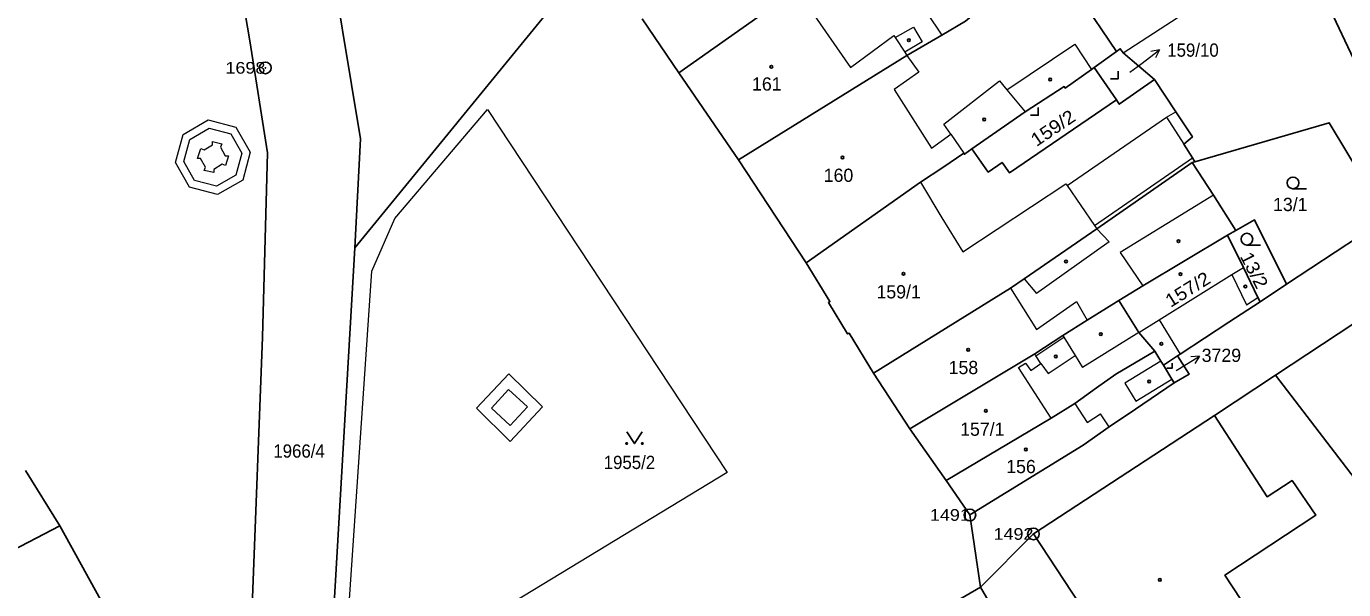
# Model space of a CAD drawing. Extents: x -679733 to -673243, y -1075091 to -1066557.
# Drawn here: x -676396.8 to -676227.8, y -1071687 to -1071614.6 of the extents above; entities that cross this region are included whole.
import ezdxf
from ezdxf.enums import TextEntityAlignment as Align

# ---------------------------------------------------------------- set-up
doc = ezdxf.new("R2010")
doc.units = 0
doc.header["$LTSCALE"] = 0.68
for name, color, linetype, lineweight in [('1', 7, 'Continuous', 25), ('3', 7, 'Continuous', 25), ('4', 7, 'Continuous', 13), ('5', 7, 'Continuous', 25), ('7', 7, 'Continuous', 13), ('8', 7, 'Continuous', 25)]:
    doc.layers.add(name, color=color, linetype=linetype, lineweight=lineweight)
doc.layers.add('2', color=7, linetype='Continuous')

msp = doc.modelspace()

# ---------------------------------------------------------------- linework, layer by layer
at = {"layer": '1'}
for p, q in [((-676323.65, -1071605.06), (-676354.68, -1071643.07)), ((-676265.58, -1071605.04), (-676256.92, -1071617.84)), ((-676317.8, -1071613.66), (-676313.09, -1071620.56)), ((-676256.92, -1071617.84), (-676259.79, -1071619.88)), ((-676256.93, -1071624.07), (-676259.79, -1071619.88)), ((-676305.44, -1071631.74), (-676296.73, -1071644.97)), ((-676247.22, -1071632.12), (-676246.86, -1071632.02)), ((-676242.69, -1071641.44), (-676241.62, -1071640.83)), ((-676238.49, -1071650), (-676235.09, -1071647.75)), ((-676250.9, -1071658.13), (-676249.09, -1071656.93)), ((-676288.1, -1071659.17), (-676283.43, -1071666.32)), ((-676283.43, -1071666.32), (-676278.79, -1071672.97)), ((-676385.21, -1071692.07), (-676392.51, -1071678.79)), ((-676274.38, -1071686.65), (-676283.55, -1071691.97))]:
    msp.add_line(p, q, dxfattribs=at)
for points in [[(-676409.82, -1071487.07), (-676395.79, -1071511.68), (-676384.03, -1071532.68), (-676381.89, -1071539.87), (-676376.19, -1071569.34), (-676368.13, -1071616.48), (-676365.86, -1071630.87), (-676366.52, -1071654.54), (-676369.19, -1071723.74), (-676369.58, -1071729.58), (-676368.92, -1071732.38)], [(-676254.27, -1071592.33), (-676250.44, -1071598.38), (-676250.16, -1071598.2), (-676242.88, -1071609.41), (-676233.68, -1071603.54), (-676226.09, -1071619.69), (-676225.97, -1071624.14), (-676221.28, -1071632.65), (-676219.43, -1071633.33)], [(-676281.75, -1071598.41), (-676282.81, -1071599.16), (-676286.84, -1071602.07), (-676288.17, -1071603), (-676292.09, -1071605.74), (-676313.09, -1071620.56), (-676305.44, -1071631.74)], [(-676354.68, -1071643.07), (-676353.93, -1071629.04), (-676358.61, -1071600.83)], [(-676272.57, -1071610.82), (-676276.28, -1071613.95), (-676279.35, -1071615.75), (-676283.81, -1071618.35), (-676305.44, -1071631.74)], [(-676256.92, -1071617.84), (-676256.44, -1071617.49), (-676256.07, -1071618.02), (-676252.04, -1071621.43)], [(-676259.79, -1071619.88), (-676260.14, -1071620.14), (-676263.49, -1071622.54), (-676263.63, -1071622.34), (-676268.66, -1071625.61), (-676275.49, -1071630.36)], [(-676252.04, -1071621.43), (-676256.57, -1071624.61), (-676256.93, -1071624.07)], [(-676246.86, -1071632.02), (-676247.18, -1071631.5), (-676248.3, -1071629.73), (-676247.17, -1071628.82), (-676249.29, -1071625.6), (-676252.04, -1071621.43)], [(-676256.93, -1071624.07), (-676270.67, -1071633.41), (-676271.6, -1071632.09), (-676273.39, -1071633.33), (-676275.49, -1071630.36)], [(-676246.86, -1071632.02), (-676229.61, -1071626.99), (-676224.86, -1071634.98), (-676225.72, -1071641.56)], [(-676275.49, -1071630.36), (-676276.45, -1071631.03), (-676276.53, -1071630.92), (-676279.21, -1071632.74), (-676282.09, -1071634.64), (-676296.73, -1071644.97)], [(-676247.22, -1071632.12), (-676259.45, -1071640.64), (-676268.78, -1071647.06), (-676270.54, -1071648.26), (-676288.1, -1071659.17)], [(-676241.62, -1071640.83), (-676244.47, -1071636.28), (-676247.22, -1071632.12)], [(-676241.62, -1071640.83), (-676239.22, -1071639.46), (-676235.09, -1071647.75), (-676225.72, -1071641.56)], [(-676242.69, -1071641.44), (-676253.54, -1071647.95), (-676256.61, -1071649.82)], [(-676238.49, -1071650), (-676238.77, -1071649.43), (-676240.63, -1071645.59), (-676242.69, -1071641.44)], [(-676359.43, -1071729.07), (-676360.28, -1071727.35), (-676359.84, -1071726.37), (-676357.99, -1071700.53), (-676354.68, -1071643.07)], [(-676296.73, -1071644.97), (-676293.69, -1071649.96), (-676293.9, -1071650.09), (-676291.44, -1071654.13), (-676291.24, -1071654.01), (-676288.1, -1071659.17)], [(-676244.34, -1071664.59), (-676236.52, -1071659.42), (-676214.28, -1071644.72)], [(-676256.61, -1071649.82), (-676260.69, -1071652.36), (-676263.83, -1071654.31), (-676267.42, -1071656.68), (-676283.43, -1071666.32)], [(-676252, -1071656.35), (-676254.05, -1071653.94), (-676256.61, -1071649.82)], [(-676249.09, -1071656.93), (-676248.74, -1071656.71), (-676242.52, -1071652.62), (-676238.49, -1071650)], [(-676252, -1071656.35), (-676256.99, -1071659.28), (-676259.51, -1071661.04), (-676262.28, -1071663.06), (-676265.3, -1071664.96), (-676278.79, -1071672.97), (-676275.74, -1071677.38)], [(-676250.9, -1071658.13), (-676251.22, -1071657.62), (-676252, -1071656.35)], [(-676249.09, -1071656.93), (-676247.6, -1071659.3), (-676249.51, -1071660.4)], [(-676249.51, -1071660.4), (-676249.8, -1071659.93), (-676250.9, -1071658.13)], [(-676236.52, -1071659.42), (-676224.9, -1071674.63), (-676205.45, -1071666.89)], [(-676275.74, -1071677.38), (-676261.19, -1071668.4), (-676257.85, -1071666.06), (-676254.49, -1071663.79), (-676249.51, -1071660.4)], [(-676229.7, -1071705.35), (-676243, -1071685.11), (-676231.35, -1071677.42), (-676234.39, -1071672.97), (-676237.6, -1071675.04), (-676244.34, -1071664.59), (-676267.58, -1071679.82)], [(-676417.9, -1071694.39), (-676399.59, -1071682.48), (-676392.51, -1071678.79), (-676396.92, -1071671.69)], [(-676275.74, -1071677.38), (-676274.38, -1071686.65), (-676267.58, -1071679.82)], [(-676267.58, -1071679.82), (-676259.71, -1071691.8), (-676259.99, -1071691.98), (-676251.12, -1071705.37), (-676250.88, -1071705.21), (-676242.83, -1071717.44)], [(-676253.8, -1071717.85), (-676256.22, -1071714.01), (-676256.09, -1071713.94), (-676260.54, -1071706.43), (-676261.93, -1071707.38), (-676265.5, -1071701.11), (-676264.81, -1071700.51), (-676266.67, -1071697.53), (-676267.32, -1071697.96), (-676270.72, -1071692.9), (-676274.38, -1071686.65)]]:
    msp.add_lwpolyline(points, dxfattribs=at)
at = {"layer": '3'}
for p, q in [((-676234.273, -1071635.47), (-676232.523, -1071635.47)), ((-676240.183, -1071642.7), (-676238.433, -1071642.7))]:
    msp.add_line(p, q, dxfattribs=at)
for points in [[(-676257.711, -1071621.37), (-676256.71, -1071621.37), (-676256.71, -1071620.37)], [(-676267.971, -1071626.02), (-676266.97, -1071626.02), (-676266.97, -1071625.02)], [(-676250.451, -1071658.54), (-676249.78, -1071658.54), (-676249.78, -1071657.87)], [(-676319.78, -1071666.699), (-676318.78, -1071668.2), (-676317.78, -1071666.699)]]:
    msp.add_lwpolyline(points, dxfattribs=at)
for centre, radius in [((-676234.2729, -1071634.7198), 0.75), ((-676240.1829, -1071641.9498), 0.75), ((-676319.78, -1071668.1995), 0.1), ((-676317.78, -1071668.1995), 0.1)]:
    msp.add_circle(centre, radius, dxfattribs=at)
at = {"layer": '4'}
for p, q in [((-676256.07, -1071618.02), (-676242.88, -1071609.41)), ((-676297.1, -1071611.14), (-676291.07, -1071619.88)), ((-676281.28, -1071612.88), (-676279.35, -1071615.75)), ((-676291.07, -1071619.88), (-676285.51, -1071615.77)), ((-676285.51, -1071615.77), (-676285.32, -1071616.06)), ((-676285.32, -1071616.06), (-676282.97, -1071614.7)), ((-676282.97, -1071614.7), (-676281.85, -1071616.61)), ((-676285.32, -1071616.06), (-676284.09, -1071617.92)), ((-676281.85, -1071616.61), (-676284.09, -1071617.92)), ((-676270.98, -1071622.76), (-676262.29, -1071616.9)), ((-676262.29, -1071616.9), (-676260.14, -1071620.14)), ((-676284.09, -1071617.92), (-676283.81, -1071618.35)), ((-676283.81, -1071618.35), (-676282.31, -1071620.5)), ((-676282.31, -1071620.5), (-676285.45, -1071622.72)), ((-676279.08, -1071627.16), (-676271.92, -1071621.6)), ((-676271.92, -1071621.6), (-676270.98, -1071622.76)), ((-676285.45, -1071622.72), (-676280.66, -1071630.28)), ((-676270.98, -1071622.76), (-676268.66, -1071625.61)), ((-676349.55, -1071639.3), (-676337.64, -1071625.28)), ((-676337.64, -1071625.28), (-676306.9, -1071671.93)), ((-676250.49, -1071626.26), (-676249.29, -1071625.6)), ((-676376.72, -1071628.5), (-676373.5, -1071626.63)), ((-676373.5, -1071626.63), (-676369.92, -1071627.55)), ((-676369.92, -1071627.55), (-676368.11, -1071630.79)), ((-676278.18, -1071628.48), (-676279.08, -1071627.16)), ((-676263.25, -1071635.07), (-676250.49, -1071626.26)), ((-676250.49, -1071626.26), (-676248.3, -1071629.73)), ((-676377.7, -1071632.12), (-676376.72, -1071628.5)), ((-676376.62, -1071631.98), (-676375.86, -1071629.16)), ((-676375.86, -1071629.16), (-676373.36, -1071627.7)), ((-676373.36, -1071627.7), (-676370.58, -1071628.41)), ((-676370.58, -1071628.41), (-676369.18, -1071630.92)), ((-676280.66, -1071630.28), (-676278.18, -1071628.48)), ((-676278.18, -1071628.48), (-676276.53, -1071630.92)), ((-676374.87, -1071631.6), (-676374.44, -1071630.31)), ((-676374.44, -1071630.31), (-676374.02, -1071630.47)), ((-676374.02, -1071630.47), (-676372.92, -1071629.83)), ((-676372.93, -1071629.42), (-676371.74, -1071629.7)), ((-676372.92, -1071629.83), (-676372.93, -1071629.42)), ((-676371.74, -1071629.7), (-676371.92, -1071630.11)), ((-676371.92, -1071630.11), (-676371.31, -1071631.23)), ((-676369.18, -1071630.92), (-676369.92, -1071633.71)), ((-676368.11, -1071630.79), (-676369.06, -1071634.37)), ((-676375.89, -1071635.27), (-676377.7, -1071632.12)), ((-676375.23, -1071634.4), (-676376.62, -1071631.98)), ((-676374.46, -1071631.59), (-676374.87, -1071631.6)), ((-676373.82, -1071632.69), (-676374.46, -1071631.59)), ((-676373.99, -1071633.11), (-676373.82, -1071632.69)), ((-676371.69, -1071632.33), (-676372.78, -1071632.99)), ((-676371.28, -1071632.49), (-676371.69, -1071632.33)), ((-676371.31, -1071631.23), (-676370.9, -1071631.23)), ((-676370.9, -1071631.23), (-676371.28, -1071632.49)), ((-676259.76, -1071640.19), (-676247.18, -1071631.5)), ((-676372.77, -1071633.4), (-676373.99, -1071633.11)), ((-676372.78, -1071632.99), (-676372.77, -1071633.4)), ((-676369.92, -1071633.71), (-676372.42, -1071635.13)), ((-676369.06, -1071634.37), (-676372.28, -1071636.2)), ((-676372.28, -1071636.2), (-676375.89, -1071635.27)), ((-676372.42, -1071635.13), (-676375.23, -1071634.4)), ((-676282.09, -1071634.64), (-676279.35, -1071639.2)), ((-676276.65, -1071643.59), (-676263.42, -1071634.82)), ((-676263.42, -1071634.82), (-676263.25, -1071635.07)), ((-676263.25, -1071635.07), (-676259.76, -1071640.19)), ((-676244.47, -1071636.28), (-676256.46, -1071643.66)), ((-676352.5, -1071646.08), (-676349.55, -1071639.3)), ((-676279.35, -1071639.2), (-676276.65, -1071643.59)), ((-676259.76, -1071640.19), (-676259.45, -1071640.64)), ((-676259.45, -1071640.64), (-676257.88, -1071642.31)), ((-676257.88, -1071642.31), (-676267.19, -1071648.94)), ((-676256.46, -1071643.66), (-676253.54, -1071647.95)), ((-676355.69, -1071692.9), (-676352.5, -1071646.08)), ((-676242.11, -1071646.51), (-676240.63, -1071645.59)), ((-676268.78, -1071647.06), (-676267.19, -1071648.94)), ((-676251.45, -1071652.32), (-676242.11, -1071646.51)), ((-676242.11, -1071646.51), (-676240.23, -1071650.38)), ((-676270.54, -1071648.26), (-676267.19, -1071653.57)), ((-676240.23, -1071650.38), (-676238.77, -1071649.43)), ((-676267.19, -1071653.57), (-676262.06, -1071649.96)), ((-676262.06, -1071649.96), (-676260.69, -1071652.36)), ((-676254.05, -1071653.94), (-676251.45, -1071652.32)), ((-676251.45, -1071652.32), (-676248.74, -1071656.71)), ((-676267.26, -1071656.93), (-676263.7, -1071654.52)), ((-676263.83, -1071654.31), (-676263.7, -1071654.52)), ((-676263.7, -1071654.52), (-676262.22, -1071656.9)), ((-676254.05, -1071653.94), (-676261.27, -1071658.43)), ((-676269.5, -1071658.42), (-676268.61, -1071657.86)), ((-676268.61, -1071657.86), (-676267.92, -1071658.83)), ((-676267.92, -1071658.83), (-676266.62, -1071657.91)), ((-676267.26, -1071656.93), (-676267.42, -1071656.68)), ((-676266.62, -1071657.91), (-676267.26, -1071656.93)), ((-676266.62, -1071657.91), (-676265.69, -1071659.22)), ((-676265.69, -1071659.22), (-676262.22, -1071656.9)), ((-676262.22, -1071656.9), (-676261.27, -1071658.43)), ((-676251.22, -1071657.62), (-676255.84, -1071660.46)), ((-676339.05, -1071663.67), (-676334.9, -1071659.25)), ((-676334.9, -1071659.25), (-676330.57, -1071663.48)), ((-676265.3, -1071664.96), (-676269.5, -1071658.42)), ((-676337.15, -1071663.64), (-676334.94, -1071661.28)), ((-676334.94, -1071661.28), (-676332.5, -1071663.47)), ((-676255.84, -1071660.46), (-676254.42, -1071662.77)), ((-676254.42, -1071662.77), (-676249.8, -1071659.93)), ((-676262.28, -1071663.06), (-676260.69, -1071665.52)), ((-676334.72, -1071667.94), (-676339.05, -1071663.67)), ((-676334.75, -1071665.89), (-676337.15, -1071663.64)), ((-676332.5, -1071663.47), (-676334.75, -1071665.89)), ((-676330.57, -1071663.48), (-676334.72, -1071667.94)), ((-676260.69, -1071665.52), (-676258.97, -1071664.41)), ((-676257.85, -1071666.06), (-676258.97, -1071664.41)), ((-676306.9, -1071671.93), (-676348.68, -1071697.31))]:
    msp.add_line(p, q, dxfattribs=at)
at = {"layer": '5'}
for centre in [(-676283.5668, -1071616.3992), (-676301.2168, -1071619.7992), (-676265.4268, -1071621.4492), (-676273.8968, -1071626.5692), (-676292.0768, -1071631.4692), (-676248.9668, -1071642.2092), (-676284.2568, -1071646.3892), (-676263.4068, -1071644.8292), (-676248.7068, -1071646.4392), (-676240.3868, -1071648.0392), (-676258.9468, -1071654.1392), (-676275.9468, -1071656.1592), (-676251.1668, -1071655.3892), (-676264.7068, -1071657.0092), (-676252.7468, -1071660.2392), (-676273.6868, -1071663.9992), (-676268.5468, -1071668.9592), (-676251.3468, -1071685.7292)]:
    msp.add_circle(centre, 0.175, dxfattribs=at)
at = {"layer": '7'}
for p, q in [((-676251.413, -1071617.644), (-676252.514, -1071617.847)), ((-676246.285, -1071656.96), (-676247.4, -1071657.066))]:
    msp.add_line(p, q, dxfattribs=at)
for points in [[(-676255.23, -1071620.51), (-676253.81, -1071619.45), (-676251.413, -1071617.644), (-676251.912, -1071618.647)], [(-676249.25, -1071658.81), (-676248.83, -1071658.55), (-676246.285, -1071656.96), (-676246.869, -1071657.915)]]:
    msp.add_lwpolyline(points, dxfattribs=at)
at = {"layer": '8'}
for centre, radius in [((-676366.15, -1071619.9398), 0.75), ((-676366.15, -1071619.9398), 0.03), ((-676275.74, -1071677.3798), 0.75), ((-676275.74, -1071677.3798), 0.03), ((-676267.58, -1071679.8198), 0.75), ((-676267.58, -1071679.8198), 0.03)]:
    msp.add_circle(centre, radius, dxfattribs=at)

# ---------------------------------------------------------------- texts
at = {"layer": '2', "width": 0.95}
for s, p in [('159/10', (-676250.41, -1071618.509)), ('1966/4', (-676365.13, -1071670.019))]:
    msp.add_text(s, height=1.7, dxfattribs=at).set_placement(p)
at = {"layer": '2'}
for s, p in [('161', (-676301.799, -1071622.86)), ('160', (-676292.599, -1071634.59)), ('13/1', (-676234.62, -1071638.34)), ('159/1', (-676284.88, -1071649.56)), ('158', (-676276.569, -1071659.29)), ('157/1', (-676274.14, -1071667.21)), ('156', (-676269.179, -1071672.009))]:
    msp.add_text(s, height=1.7, dxfattribs=at).set_placement(p, align=Align.CENTER)
at = {"layer": '2', "width": 1.1}
for s, rotation, p in [('159/2', 34, (-676264.5968, -1071628.3704)), ('13/2', 297, (-676240.0055, -1071646.3231)), ('157/2', 32, (-676247.3289, -1071649.1228))]:
    msp.add_text(s, height=1.7, rotation=rotation, dxfattribs=at).set_placement(p, align=Align.CENTER)
at = {"layer": '2'}
msp.add_text('3729', height=1.7, dxfattribs=at).set_placement((-676245.99, -1071657.72))
at = {"layer": '2', "width": 0.95}
msp.add_text('1955/2', height=1.7, dxfattribs=at).set_placement((-676319.429, -1071671.479), align=Align.CENTER)
at = {"layer": '8', "width": 1.15}
for s, p in [('1698', (-676366.149, -1071620.69)), ('1491', (-676275.739, -1071678.129)), ('1492', (-676267.579, -1071680.57))]:
    msp.add_text(s, height=1.5, dxfattribs=at).set_placement(p, align=Align.RIGHT)

doc.saveas('drawing.dxf')
